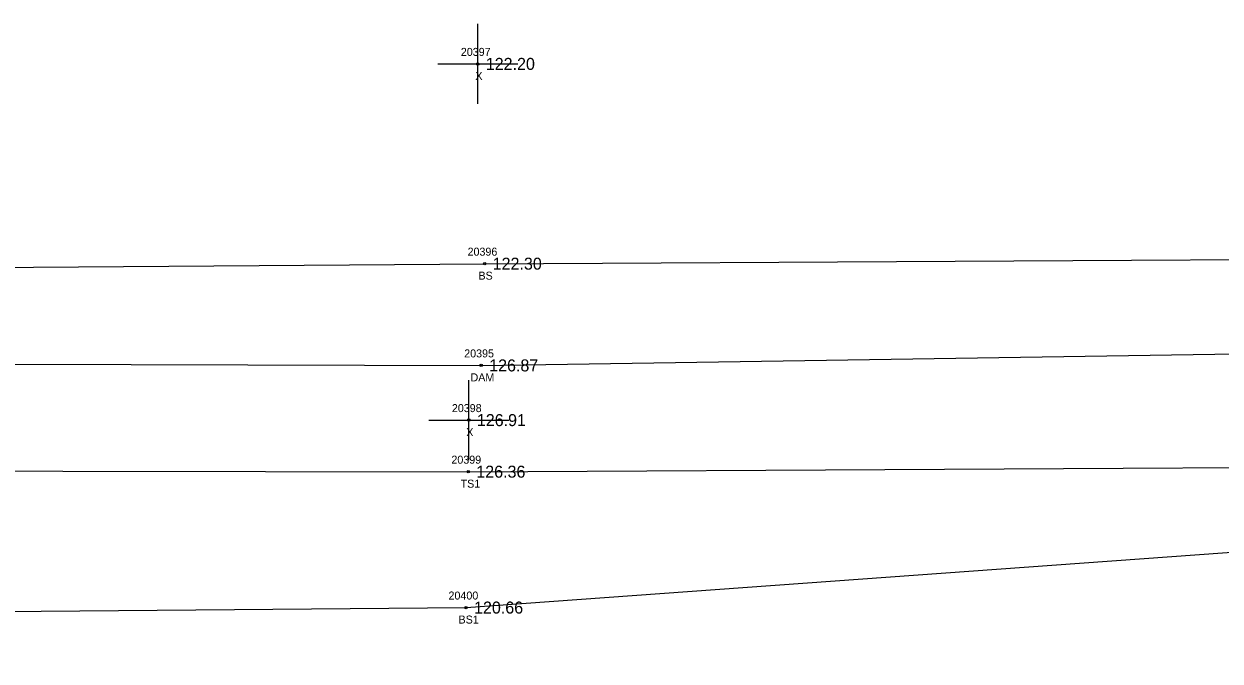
# Model space of a CAD drawing. Extents: x 2375812 to 2377225, y 1024470 to 1025135.
# Drawn here: x 2376931.3 to 2377080.8, y 1025040.9 to 1025120.6 of the extents above; entities that cross this region are included whole.
import ezdxf

# ---------------------------------------------------------------- set-up
doc = ezdxf.new("R2010")
doc.units = 0
for name, color, linetype in [('RD_DTM_BkLn2', 7, 'Continuous'), ('RD_DTM_BkLn_txCode', 7, 'Continuous'), ('RD_EX_Dam', 7, 'Continuous'), ('RD_EX_Dam_txCode', 7, 'Continuous'), ('RD_EX_Misc', 7, 'Continuous'), ('RD_EX_Misc_txCode', 7, 'Continuous'), ('RD_EX_TX_Dam_ELEV', 7, 'Continuous'), ('RD_EX_TX_Misc_ELEV', 7, 'Continuous'), ('RD_SMD_Locator', 7, 'Continuous')]:
    doc.layers.add(name, color=color, linetype=linetype)

msp = doc.modelspace()

# ---------------------------------------------------------------- linework, layer by layer
at = {"layer": 'RD_DTM_BkLn2'}
for points in [[(2376552.99, 1025053.79), (2376560.85, 1025063.21), (2376567.06, 1025075.76), (2376572.77, 1025085.75), (2376582.8, 1025094.03), (2376679.85, 1025092.48), (2376779.73, 1025094.91), (2376887.32, 1025089.81), (2376988.9, 1025090.57), (2377106.48, 1025091.22), (2377202.62, 1025093.89)], [(2376580.3, 1025079.96), (2376576.42, 1025074.43), (2376572.95, 1025066.08), (2376567.78, 1025062.13), (2376680.13, 1025064), (2376781.64, 1025064.6), (2376885.5, 1025064.7), (2376986.85, 1025064.56), (2377105.91, 1025065.21), (2377201.99, 1025063.63)], [(2376554.71, 1025040.88), (2376679.34, 1025046.02), (2376781.14, 1025046.61), (2376885.14, 1025046.71), (2376986.57, 1025047.57), (2377105.91, 1025056.21), (2377201.82, 1025050.7)]]:
    msp.add_lwpolyline(points, dxfattribs=at)
at = {"layer": 'RD_EX_Dam'}
msp.add_lwpolyline([(2376580.3, 1025079.96), (2376679.85, 1025076.24), (2376781.56, 1025078.14), (2376886.41, 1025078.13), (2376988.46, 1025077.85), (2377107.1, 1025079.69), (2377202.68, 1025079.96)], dxfattribs=at)
at = {"layer": 'RD_EX_Misc'}
for p, q in [((2376988.04, 1025110.55), (2376988.04, 1025120.55)), ((2376983.04, 1025115.55), (2376993.04, 1025115.55)), ((2376986.92, 1025066.01), (2376986.92, 1025076.01)), ((2376981.92, 1025071.01), (2376991.92, 1025071.01))]:
    msp.add_line(p, q, dxfattribs=at)
at = {"layer": 'RD_SMD_Locator'}
for centre in [(2376988.04, 1025115.55), (2376988.9, 1025090.57), (2376988.46, 1025077.85), (2376986.92, 1025071.01), (2376986.85, 1025064.56), (2376986.57, 1025047.57)]:
    msp.add_circle(centre, 0.15, dxfattribs=at)

# ---------------------------------------------------------------- texts
at = {"layer": 'RD_DTM_BkLn_txCode'}
for s, p in [('20396', (2376986.76, 1025091.57)), ('BS', (2376988.12, 1025088.57)), ('20399', (2376984.74, 1025065.56)), ('TS1', (2376985.89, 1025062.56)), ('20400', (2376984.38, 1025048.57)), ('BS1', (2376985.63, 1025045.57))]:
    msp.add_text(s, height=1, dxfattribs=at).set_placement(p)
at = {"layer": 'RD_EX_Dam_txCode'}
for s, p in [('20395', (2376986.34, 1025078.85)), ('DAM', (2376987.13, 1025075.85))]:
    msp.add_text(s, height=1, dxfattribs=at).set_placement(p)
at = {"layer": 'RD_EX_Misc_txCode'}
for s, p in [('20397', (2376985.92, 1025116.55)), ('X', (2376987.73, 1025113.55)), ('20398', (2376984.8, 1025072.01)), ('X', (2376986.6, 1025069.01))]:
    msp.add_text(s, height=1, dxfattribs=at).set_placement(p)
at = {"layer": 'RD_EX_TX_Dam_ELEV'}
msp.add_text('126.87', height=1.5, dxfattribs=at).set_placement((2376989.46, 1025077.1))
at = {"layer": 'RD_EX_TX_Misc_ELEV'}
for s, p in [('122.20', (2376989.04, 1025114.8)), ('122.30', (2376989.9, 1025089.82)), ('126.91', (2376987.92, 1025070.26)), ('126.36', (2376987.85, 1025063.81)), ('120.66', (2376987.57, 1025046.82))]:
    msp.add_text(s, height=1.5, dxfattribs=at).set_placement(p)

doc.saveas('drawing.dxf')
